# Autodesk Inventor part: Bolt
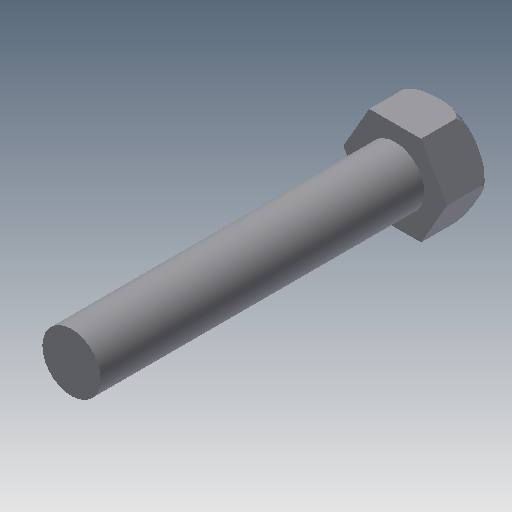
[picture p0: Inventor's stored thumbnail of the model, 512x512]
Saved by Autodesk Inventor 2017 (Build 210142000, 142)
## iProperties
Shininess: 77.0
Length Units: 11269
Angle Units: 11279
Time Units: 11290
Mass Units: 11283
Length Display Precision: 3
Angle Display Precision: 2
Created: 2002-02
Part Number: Bolt
Document SubType Name: Modeling
Designer: ***
Density: 1 g/cm^3
Material: Generic
Appearance: Default
Density: 0.0
Volumn: 0.0
Area: 0.0
PropertySet Name: Model Information
Control State: 0
Master: False
Checked Out: False
Author: ***
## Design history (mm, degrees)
sketch "Sketch1"
  geometry: C1 r 4 at (0, 0)
  constraints: 1 centre point
  dimensions: "d0" = 8 diameter of C1
extrude "Extrusion1" new body sketch "Sketch1" stored distance "d1" = 3.5; taper "d2" = 0 deg
fillet "Fillet1" dims "d3" = 1
sketch "Sketch2"
  geometry: L1 (4, 0)-(2, -3.464); L2 (2, -3.464)-(-2, -3.464); L3 (-2, -3.464)-(-4, 0); L4 (-4, 0)-(-2, 3.464); L5 (-2, 3.464)-(2, 3.464); L6 (2, 3.464)-(4, 0); 2 further points
  constraints: 12 end point, 1 coincident, 11 other
extrude "Extrusion2" sketch "Sketch2" stored distance "d4" = 3.5; taper "d5" = 0 deg
sketch "Sketch3"
  geometry: C1 r 2.25 at (0, 0)
  constraints: 1 centre point
  dimensions: "d6" = 4.5 diameter of C1
extrude "Extrusion3" join sketch "Sketch3" distance "d7" = 25; taper "d8" = 0 deg
body "Solid1"
